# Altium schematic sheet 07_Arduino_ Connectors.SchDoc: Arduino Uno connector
size A4; Date: 2/4/2015; Author: P.A.; CompanyName: STMicroelectronics; Organization: Microcontrollers Division; Address1: 12, Rue Jules HOROWITZ; Address2: 38019 Grenoble; Address3: FRANCE; DocumentNumber: 10; Revision: E-01; SheetNumber: 10; SheetTotal: 12; Project: STM32F413H-DISCO
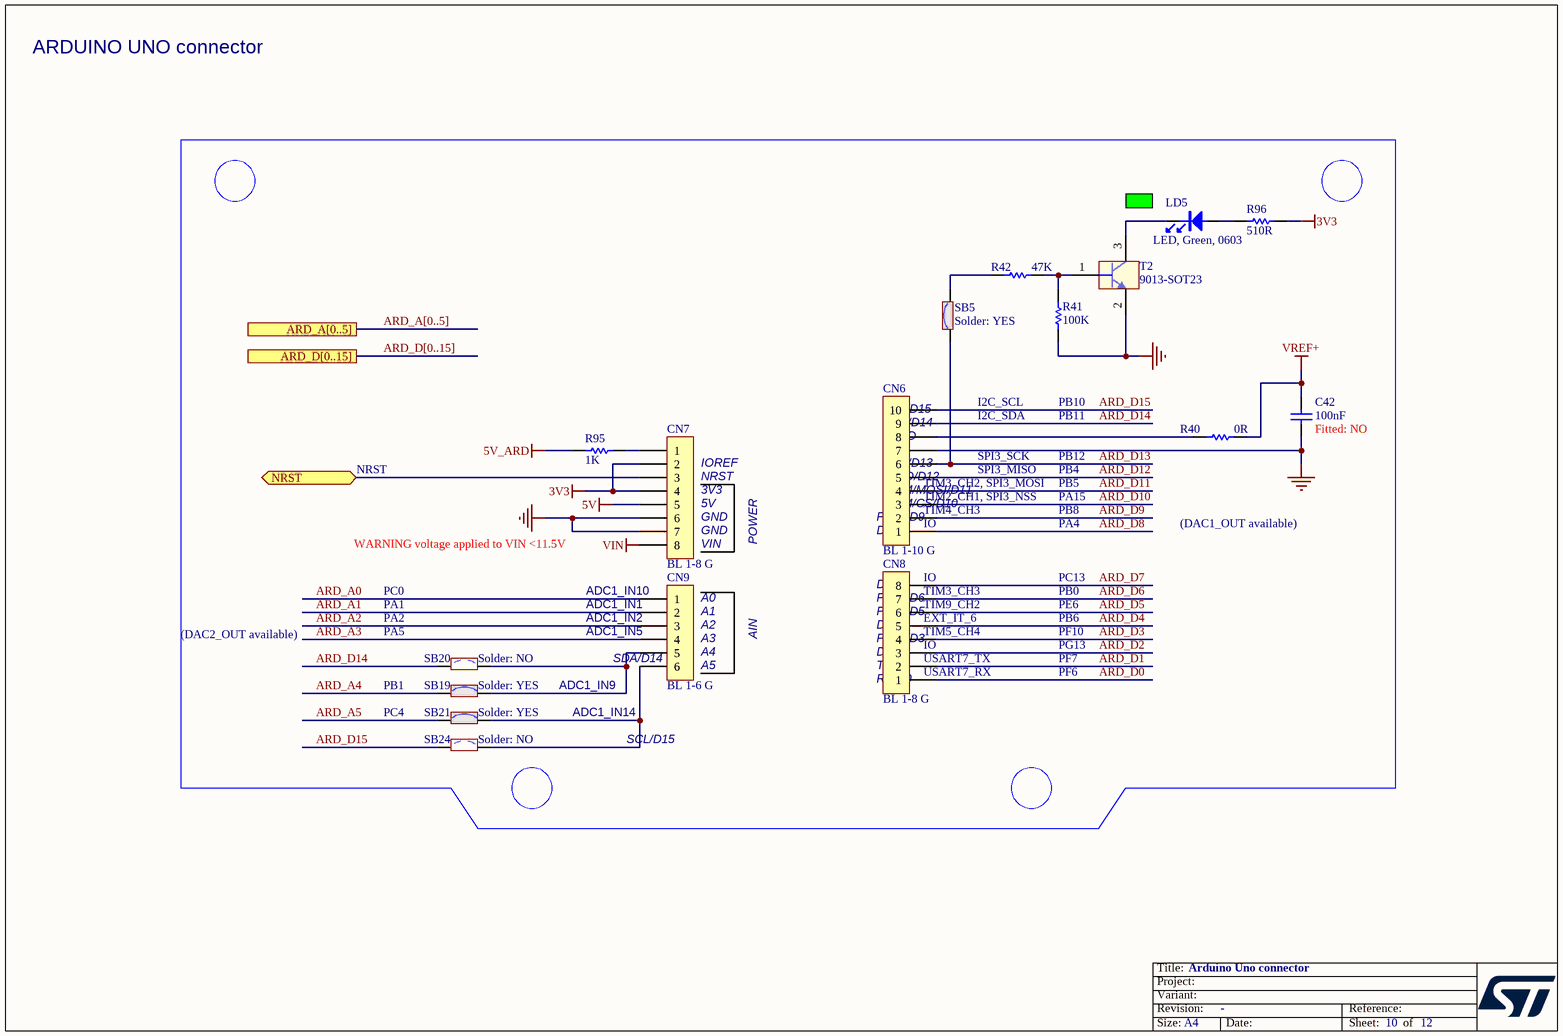
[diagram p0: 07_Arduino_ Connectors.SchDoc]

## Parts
C42  100nF  Fitted: NO  [C0402]
CN6  BL 1-10 G  [CON_FISCHER_BL1-10-G]
CN7  BL 1-8 G  [CON_FISCHER_BL1-8-G]
CN8  BL 1-8 G  [CON_FISCHER_BL1-8-G]
CN9  BL 1-6 G  [CON_FISCHER_BL1-6-G]
LD5  LED, Green, 0603  [LED_0603_GREEN]
R40  0R  [R0402]
R41  100K  [R0402]
R42  47K  [R0402]
R95  1K  [R0603]
R96  510R  [R0402]
SB5  Solder: YES  [SOLDER-BRIDGE_R0603-0R]  (hidden comment: SB_ON)
SB19  Solder: YES  [SOLDER-BRIDGE_R0603-0R]  (hidden comment: SB_ON)
SB20  Solder: NO  [SOLDER-BRIDGE_R0603-0R]  (hidden comment: SB_OFF)
SB21  Solder: YES  [SOLDER-BRIDGE_R0603-0R]  (hidden comment: SB_ON)
SB24  Solder: NO  [SOLDER-BRIDGE_R0603-0R]  (hidden comment: SB_OFF)
T2  9013-SOT23  [NPN_SOT23]

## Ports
ARD_A[0..5], ARD_D[0..15], NRST (bidir)

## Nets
3V3: CN7.2 CN7.4 R96.2
5V: CN7.5
5V_ARD: R95.1
GND: C42.1 CN6.7 CN7.6 CN7.7 R41.1 T2.2(E)
VIN: CN7.8
VREF+: C42.2 R40.2
ARD_A0: CN9.1
ARD_A1: CN9.2
ARD_A2: CN9.3
ARD_A3: CN9.4
ARD_A4: SB19.1
ARD_A5: SB21.1
ARD_D0: CN8.1
ARD_D1: CN8.2
ARD_D2: CN8.3
ARD_D3: CN8.4
ARD_D4: CN8.5
ARD_D5: CN8.6
ARD_D6: CN8.7
ARD_D7: CN8.8
ARD_D8: CN6.1
ARD_D9: CN6.2
ARD_D10: CN6.3
ARD_D11: CN6.4
ARD_D12: CN6.5
ARD_D13: CN6.6 SB5.1
ARD_D14: CN6.9 SB20.1
ARD_D15: CN6.10 SB24.1
NRST: CN7.3 ; port NRST
NetCN6_8: CN6.8 R40.1
NetCN7_1: CN7.1 R95.2
NetCN9_5: CN9.5 SB19.2 SB20.2
NetCN9_6: CN9.6 SB21.2 SB24.2
NetLD5_1: LD5.1 R96.1
NetLD5_2: LD5.2 T2.3(C)
NetR41_2: R41.2 R42.2 T2.1(B)
NetR42_1: R42.1 SB5.2

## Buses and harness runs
bus ARD_A[0..5] = port ARD_A[0..5]
bus ARD_D[0..15] = port ARD_D[0..15]

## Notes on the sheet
- ARDUINO UNO connector
- (near CN6) SDA/D14
- (near CN6) SCL/D15
- (near CN6) AVDD
- I2C_SCL
- I2C_SDA
- PB10
- PB11
- NRST
- (near CN7) IOREF
- (near CN7) NRST
- (near CN7) 3V3
- (near CN7) 5V
- (near CN7) GND
- (near CN6) PWM/D9
- (near CN6) PWM/CS/D10
- (near CN6) SCK/D13
- (near CN6) MISO/D12
- (near CN6) PWM/MOSI/D11
- (near CN6) GND
- (near CN6) TIM4_CH3
- (near CN6) TIM2_CH1, SPI3_NSS
- (near CN6) TIM3_CH2, SPI3_MOSI
- SPI3_SCK
- SPI3_MISO
- PB8
- PA15
- PB5
- PB4
- PB12
- WARNING voltage applied to VIN <11.5V
- (near CN7) VIN
- POWER
- (near CN6) D8
- (near CN8) IO
- (near CN6) IO
- PC13
- PA4
- (DAC1_OUT available)
- (DAC2_OUT available)
- PC0
- PA1
- PA2
- PA5
- (near CN9) ADC1_IN5
- (near CN9) ADC1_IN2
- (near CN9) ADC1_IN1
- (near CN9) ADC1_IN10
- (near CN9) A0
- (near CN9) A1
- (near CN9) A2
- (near CN9) A3
- (near CN9) A4
- AIN
- (near CN8) D2
- (near CN8) D4
- (near CN8) PWM/D3
- (near CN8) PWM/D5
- (near CN8) PWM/D6
- (near CN8) D7
- (near CN8) TIM5_CH4
- (near CN8) TIM9_CH2
- (near CN8) TIM3_CH3
- (near CN8) EXT_IT_6
- PG13
- PF10
- PB6
- PE6
- PB0
- PB1
- PC4
- ADC1_IN9
- ADC1_IN14
- SDA/D14
- (near CN9) A5
- (near CN8) RX/D0
- (near CN8) TX/D1
- (near CN8) USART7_RX
- (near CN8) USART7_TX
- PF6
- PF7
- SCL/D15

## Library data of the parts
C42 = Cap_100nF_X7R_10%_0402: Capacitor,100nF,16V,X7R,10%,0402,YAGEO; Manuf_Part_1: CC0402KRX7R7BB104; Ordered_By: Subcon
CN6 = Header 10X1_Female_THT: Header, 10-Pin, Single row, female, THT, 2.54; Manuf_1: Fischer Electronik; Fitted: YES; Ordered_By: Subcon
CN7 CN8 = Header 8X1_Female_THT: Header, 8-Pins, Single row, female, THT, 2.54; Manuf_1: Fischer Electronik; Fitted: YES; Ordered_By: Subcon
CN9 = Header 6X1_Female_THT: Header, 6-Pins, Single row, female THT, 2.54; Manuf_1: Fischer Electronik; Fitted: YES; Ordered_By: Subcon
LD5 = LED_green: Manuf_1: everlight; Manuf_Part_1: 19-213SYGC/S530-E2/TR8; ECCN_US/EU: EAR99/NEC; Fitted: YES; Ordered_By: Subcon
R40 = Res_0_5%_0402: Resistor,0R,0402,5%,YAGEO; Manuf_Part_1: RC0402JR-070RL; Fitted: YES; Order_Code: 2363467; Ordered_By: Subcon
R41 = Res_100K_1%_0402: Resistor,100K,0402,1%,YAGEO; Manuf_Part_1: RC0402FR-07100KL; Manuf_Part_2: RT0402FRE07100KL; Fitted: YES; Ordered_By: Subcon
R42 = Res_47K_1%_0402: Resistor,47K,0402,1%,YAGEO; Manuf_Part_1: RC0402FR-0747KL; Fitted: YES; Order_Code: 9239430; Ordered_By: Subcon
R95 = Res_1K_1%_0603: Resistor,1K,0603,1%,YAGEO; Manuf_Part_1: RC0603FR-071KL; Fitted: YES; Ordered_By: Subcon
R96 = Res_510_1%_0402: Resistor,510R,0402,1%,YAGEO; Manuf_Part_1: RC0402FR-07510L; Fitted: YES; Ordered_By: Subcon
SB5 SB19 SB21 = SB_ON: Solder Bridge ON; Ordered_by: Subcon
SB20 SB24 = SB_OFF: Solder Bridge OFF; Fitted: NO; Ordered_By: Subcon
T2 = 9013-SOT23: NPN Bipolar Transistor; Manuf_1: NXP; Manuf_Part_1: BSR14; ECCN_US/EU: EAR99/NEC; Fitted: YES; Order_Code: 1081310; Ordered_By: Subcon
